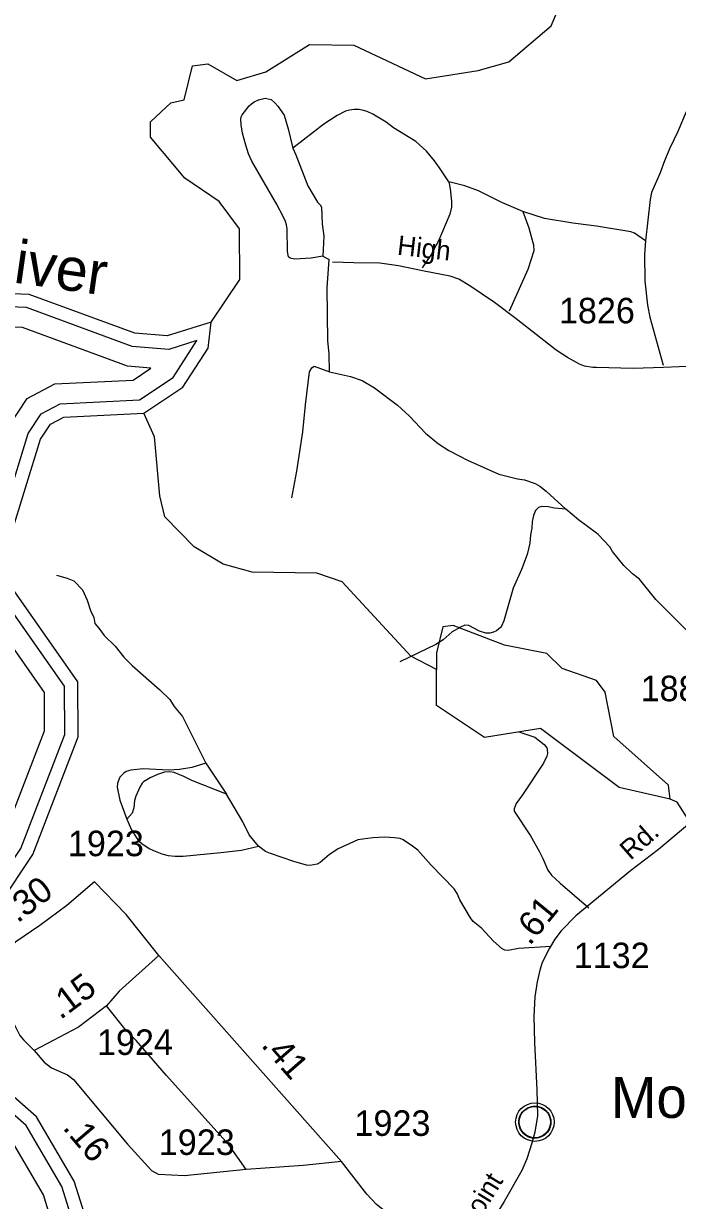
# Model space of a CAD drawing. Extents: x 2104537 to 2336408, y 34176 to 229611.
# Drawn here: x 2193201 to 2196405, y 68278 to 74040 of the extents above; entities that cross this region are included whole.
import ezdxf

# ---------------------------------------------------------------- set-up
doc = ezdxf.new("R2010")
doc.units = 0
for name, color, linetype in [('Exist Civil Demographics Community CELL', 7, 'Continuous'), ('Exist Civil Demographics Community Label', 7, 'Continuous'), ('Exist Hydrographic Buffer Line', 7, 'Continuous'), ('Exist Hydrographic Creek Single Shore', 7, 'Continuous'), ('Exist Hydrographic Misc Water Feature', 7, 'Continuous'), ('Exist Hydrographic River Shore', 7, 'Continuous'), ('Exist Hydrographic River Shore Label', 7, 'Continuous'), ('Exist Road Non-System Type 51', 7, 'Continuous'), ('Exist Road Secondary Mileage Hundredths English Label', 7, 'Continuous'), ('Exist Road Secondary Type 51 Attributed', 7, 'Continuous'), ('Exist Road Secondary Type 51 Label', 7, 'Continuous'), ('Exist Road Secondary Type 51 Number Label', 7, 'Continuous')]:
    doc.layers.add(name, color=color, linetype=linetype)

msp = doc.modelspace()

# ---------------------------------------------------------------- linework, layer by layer
at = {"layer": 'Exist Civil Demographics Community CELL'}
msp.add_lwpolyline([(2195628.7, 68673.7), (2195629.7, 68679.3), (2195631.5, 68685.9), (2195634.4, 68693.1), (2195637.3, 68698.8), (2195640.7, 68704.6), (2195644.4, 68709.7), (2195648.4, 68714.1), (2195653, 68718.7), (2195658.5, 68723.2), (2195663.9, 68726.9), (2195668.8, 68729.8), (2195673.9, 68732.2), (2195679.3, 68734.5), (2195685, 68736.3), (2195689.3, 68737.5), (2195694.1, 68738.2), (2195698.3, 68739), (2195704.6, 68739.2), (2195709.1, 68739.1), (2195714.7, 68738.8), (2195719.6, 68738.1), (2195724.5, 68737.1), (2195729.5, 68735.7), (2195734.7, 68733.8), (2195741.4, 68730.9), (2195747.6, 68727.4), (2195752.7, 68723.8), (2195757.8, 68719.8), (2195761.2, 68716.7), (2195765.3, 68712.3), (2195769.1, 68707.6), (2195772.2, 68703), (2195775.3, 68698), (2195777.8, 68692.8), (2195779.8, 68687.8), (2195781.4, 68682.8), (2195782.7, 68678.2), (2195783.8, 68672.2), (2195784.4, 68667.5), (2195784.7, 68661.5), (2195784.5, 68655.7), (2195783.9, 68650), (2195783, 68644.5), (2195781.3, 68638.4), (2195779.4, 68632.5), (2195777.2, 68627.4), (2195774, 68621.4), (2195770.7, 68616.1), (2195767.3, 68611.4), (2195763, 68606.7), (2195757.7, 68601.7), (2195752.7, 68597.6), (2195747.7, 68594.2), (2195743.4, 68591.7), (2195736.6, 68588.4), (2195729.4, 68585.7), (2195723.5, 68584.2), (2195716.9, 68582.9), (2195712.4, 68582.5), (2195708, 68582.2), (2195702.4, 68582.2), (2195698.1, 68582.6), (2195692.5, 68583.4), (2195686.5, 68584.7), (2195682, 68586), (2195676.8, 68587.8), (2195672.2, 68589.8), (2195668.3, 68592.1), (2195661.5, 68596.1), (2195655.9, 68600.4), (2195651, 68604.9), (2195646.5, 68609.8), (2195643.3, 68613.7), (2195640.4, 68617.9), (2195636.3, 68625), (2195634.5, 68628.5), (2195632.8, 68632.6), (2195630.2, 68640.8), (2195628.7, 68647.8), (2195628, 68653), (2195627.7, 68659.3), (2195627.6, 68664), (2195628.2, 68670.4)], close=True, dxfattribs=at)
for centre, radius in [((2195706.3, 68661.3), 94.3), ((2195706, 68661.6), 76.7)]:
    msp.add_circle(centre, radius, dxfattribs=at)
at = {"layer": 'Exist Hydrographic Buffer Line'}
for points in [[(2194050.2, 72487.5), (2193912.2, 72444), (2193732.4, 72458.7), (2193215.8, 72648.7), (2192875.6, 72661.9), (2192520.7, 72871), (2192188.2, 72927.8), (2192038.1, 73067.6), (2191976.1, 73208.2), (2191975, 73364)], [(2193825.2, 72352.4), (2193711, 72361.7), (2193196.4, 72550.9), (2192847, 72564.5), (2192486.3, 72777.1), (2192164, 72832.1)], [(2193769.4, 72196.7), (2193933.8, 72306.6), (2194050.2, 72487.5)], [(2193737.4, 72293.8), (2193825.2, 72352.4)], [(2193346.9, 68149.6), (2193298.6, 68305.6), (2193136.8, 68581.4), (2192844.6, 68836.2), (2192744.7, 69162), (2192677.5, 69255.2), (2192561.6, 69331.1), (2192561.6, 69585), (2192739.6, 69767), (2192974.9, 69861.3), (2193100.3, 70047), (2193304.3, 70577), (2193303.1, 70763.9), (2193008.1, 71185.1), (2192953.9, 71332.4), (2192974.8, 71560), (2193133.8, 72074.7), (2193218.8, 72204), (2193354.4, 72275.5), (2193737.4, 72293.8)], [(2193439.2, 68184.2), (2193389.3, 68345.6), (2193213.6, 68645.1), (2192930.5, 68891.9), (2192834.1, 69206.4), (2192746.6, 69327.5), (2192660.1, 69384.2), (2192660.1, 69544.9), (2192795.5, 69683.3), (2193039.6, 69781.2), (2193188.2, 70001.2), (2193402.9, 70559.1), (2193401.3, 70795.3), (2193096, 71231.1), (2193053.9, 71345.5), (2193071.9, 71540.7), (2193223.7, 72032.3), (2193287.1, 72128.7), (2193381, 72178.2), (2193769.4, 72196.7)]]:
    msp.add_lwpolyline(points, dxfattribs=at)
at = {"layer": 'Exist Hydrographic Creek Single Shore'}
msp.add_lwpolyline([(2194120.7, 72578.4), (2194260.7, 72785.8), (2194259.7, 73035.1), (2194158.6, 73168.3), (2193990.6, 73283.1), (2193822.7, 73483.2), (2193822.7, 73558.7), (2193921.8, 73651.8), (2193988.6, 73667), (2194028.6, 73833.5), (2194103.6, 73841.9), (2194245.7, 73760.4), (2194387.6, 73803.7), (2194602.7, 73937.3), (2194819.7, 73933.1), (2195170.7, 73768.9), (2195428.7, 73809.8), (2195578.8, 73852.9), (2195785.7, 74029.3), (2195949.7, 74413.2), (2196198.2, 74607.7)], dxfattribs=at)
at = {"layer": 'Exist Hydrographic Misc Water Feature'}
for points in [[(2195223.6, 70877.4), (2195098.8, 70942.2), (2194762.7, 71306.2), (2194637.8, 71348.1), (2194320.8, 71354.1), (2194178.7, 71393), (2194036.8, 71477.7), (2193893.7, 71624.9), (2193868.6, 71727.1), (2193841.8, 72016.3), (2193790.7, 72132.1)], [(2196369.7, 70241.8), (2196360.6, 70310.9), (2196092.6, 70549), (2196049.8, 70766.3), (2196007.7, 70822.9), (2195840.6, 70881.9), (2195764.8, 70955.6), (2195556.6, 70995.7), (2195305.6, 71092.4), (2195255.6, 71086.7), (2195223.6, 70959.4), (2195223.6, 70877.4)], [(2196369.7, 70241.8), (2196119.7, 70299.1), (2195733.8, 70588.7), (2195459.6, 70544.8), (2195224.7, 70700.2), (2195223.6, 70877.4)], [(2198218.8, 69113.6), (2197653.7, 68986.7), (2197403.7, 68991.5), (2197185.8, 69048.2), (2197076.7, 69155.3), (2196816.7, 69531.1), (2196664.7, 69819.5), (2196403.7, 70228), (2196369.7, 70241.8)]]:
    msp.add_lwpolyline(points, dxfattribs=at)
at = {"layer": 'Exist Hydrographic River Shore'}
for points in [[(2194120.7, 72578.4), (2193904.7, 72510.4), (2193746.6, 72523.4), (2193228.7, 72713.8), (2192894.6, 72726.8), (2192543.6, 72933.7), (2192218.6, 72989.2), (2192092.7, 73106.4), (2192041.6, 73222.3), (2192040.6, 73364.9)], [(2193790.7, 72132.1), (2193981.6, 72259.6), (2194104.7, 72450.8), (2194120.7, 72578.4)], [(2193500.8, 68207.2), (2193449.7, 68372.2), (2193264.8, 68687.5), (2192987.7, 68929.1), (2192893.6, 69236), (2192792.7, 69375.8), (2192725.7, 69419.7), (2192725.7, 69518.1), (2192832.7, 69627.6), (2193082.7, 69727.8), (2193246.7, 69970.6), (2193468.6, 70547.1), (2193466.7, 70816.2), (2193154.7, 71261.8), (2193120.6, 71354.3), (2193136.6, 71527.9), (2193283.6, 72004.1), (2193332.6, 72078.6), (2193398.7, 72113.4), (2193790.7, 72132.1)]]:
    msp.add_lwpolyline(points, dxfattribs=at)
at = {"layer": 'Exist Road Non-System Type 51'}
for p, q in [((2194667.9, 72900.6), (2194698.1, 72884.9)), ((2194093.4, 70418.9), (2194195.1, 70266))]:
    msp.add_line(p, q, dxfattribs=at)
for points in [[(2196724.4, 73706.7), (2196582.7, 73675), (2196516.9, 73664.1), (2196483.2, 73651.6), (2196463.3, 73637.2), (2196447.9, 73607), (2196407, 73510.4), (2196368.1, 73430.1), (2196340.9, 73368), (2196319.8, 73309.3), (2196276.9, 73212.7), (2196270.4, 73179), (2196248.1, 72976.7)], [(2194667.9, 72900.6), (2194610, 72891.8), (2194528.2, 72886.8), (2194507.9, 72890.5), (2194499.9, 72898.2), (2194493.5, 72924.3), (2194493.3, 73035.2), (2194490.1, 73054.3), (2194483.8, 73071.1), (2194475.4, 73092.3), (2194440.6, 73157.6), (2194319.6, 73366.3), (2194303.2, 73402), (2194290.6, 73444.3), (2194274, 73503.6), (2194266.9, 73543.5), (2194265.1, 73571.4), (2194267.7, 73582.2), (2194272.8, 73593.5), (2194306.1, 73636.2), (2194317.5, 73646.5), (2194330.1, 73656.1), (2194351.9, 73665.5), (2194385.2, 73673.7), (2194413.7, 73667.3), (2194432, 73651.5), (2194446.2, 73635.8), (2194477.5, 73590.9), (2194497.8, 73524.2), (2194519.6, 73430)], [(2195283.8, 73264), (2195238.6, 73334.1), (2195214, 73367.7), (2195174.5, 73415.7), (2195123, 73462.6), (2195014, 73529), (2194978.1, 73557.6), (2194912.9, 73595.6), (2194884.7, 73609.6), (2194866, 73614.6), (2194844.5, 73618.9), (2194820.5, 73619.7), (2194798.5, 73616.2), (2194778.7, 73610), (2194737, 73589.5), (2194671.5, 73546.5), (2194519.6, 73430)], [(2194519.6, 73430), (2194535.4, 73396.9), (2194593.5, 73245.8), (2194641.2, 73165.8), (2194653.7, 73152.8), (2194661, 73140.8), (2194663.7, 73058.4), (2194672.7, 72998.6), (2194667.9, 72900.6)], [(2195283.8, 73264), (2195291.7, 73230.7), (2195298.4, 73170.9), (2195297.5, 73140.7), (2195289.3, 73106.7), (2195235, 72979.8), (2195196.2, 72905.5), (2195153.3, 72844.3)], [(2195647.8, 73118.9), (2195544.7, 73163.8), (2195430, 73220.5), (2195363.5, 73245.7), (2195283.8, 73264)], [(2195647.8, 73118.9), (2195676.5, 73039.6), (2195693.4, 72979.9), (2195699.5, 72956.1), (2195701.5, 72926.5), (2195671.2, 72835.6), (2195580.3, 72632)], [(2196007.7, 73047.6), (2195982.1, 73051.7), (2195892.1, 73062.6), (2195752.5, 73085), (2195647.8, 73118.9)], [(2196248.1, 72976.7), (2196194.7, 73013.8), (2196176.7, 73020.1), (2196007.7, 73047.6)], [(2196248.1, 72976.7), (2196242.8, 72908.6), (2196244.6, 72780.6), (2196258.1, 72660.6), (2196269.1, 72602.9), (2196334.1, 72367.8)], [(2194699.9, 72334.3), (2194699, 72422.6), (2194692, 72486.4), (2194688.5, 72746.3), (2194698.1, 72884.9)], [(2194516.1, 71718.1), (2194540.3, 71848.6), (2194569.9, 72040.9), (2194582, 72172.9), (2194601.2, 72334.9), (2194613.1, 72354), (2194625.4, 72362.7), (2194699.9, 72334.3)], [(2194699.9, 72334.3), (2194803.5, 72312.3), (2194859.9, 72292.5), (2194920.5, 72255.9), (2195033.7, 72171.4), (2195092.4, 72118.1), (2195169.6, 72034.9), (2195234.5, 71981.8), (2195284.7, 71948.7), (2195375.3, 71901.7), (2195530.2, 71833.7), (2195620.6, 71811), (2195654.6, 71805.4), (2195708.1, 71788), (2195731.1, 71774.1), (2195761.5, 71750.5), (2195857.2, 71661.4)], [(2195857.2, 71661.4), (2195802.2, 71667.1), (2195771.2, 71673.9), (2195740.4, 71674.5), (2195724.5, 71670.2), (2195708.5, 71656.1), (2195698.8, 71631.7), (2195693.3, 71601.6), (2195691.7, 71569.8), (2195684.2, 71535.8), (2195680.8, 71495.5), (2195667.9, 71440.7), (2195640.3, 71367), (2195599.5, 71276), (2195553.4, 71116.1), (2195542.1, 71089.7), (2195537, 71083.6), (2195517.3, 71066.6), (2195504.1, 71059.3), (2195485.6, 71055.4), (2195465.3, 71055.5), (2195434.3, 71064.3), (2195382, 71091.8), (2195362.4, 71094.2), (2195341.8, 71085.1), (2195301.7, 71061.2), (2195256.6, 71022.1), (2195220.1, 71000.1), (2195044.9, 70914.9)], [(2196007.7, 71544.4), (2195919.2, 71610.7), (2195857.2, 71661.4)], [(2196764.2, 70853.2), (2196719.1, 70879), (2196581.8, 70975.2), (2196486.9, 71038), (2196446.6, 71071.3), (2196298.8, 71220.5), (2196219.4, 71319.1), (2196184.8, 71346), (2196142.3, 71385.6), (2196087.2, 71454.9), (2196072.9, 71478.4), (2196016.3, 71537.9), (2196007.7, 71544.4)], [(2193362.8, 71339.1), (2193415, 71324), (2193447.3, 71310.6), (2193489.7, 71266.8), (2193512.4, 71217.1), (2193529.1, 71165.3), (2193545.5, 71131.5), (2193550.2, 71101.6), (2193570.1, 71079.9), (2193596.6, 71044.3), (2193649.4, 70991.1), (2193692.3, 70937.4), (2193732.6, 70896.3), (2193868.4, 70777.9), (2193917, 70730.3), (2193939.3, 70696.8), (2193980.1, 70647.4), (2194093.4, 70418.9)], [(2195627.6, 70572.7), (2195705.8, 70545.6), (2195752.3, 70510.2), (2195764.8, 70494.2), (2195766.6, 70484.7), (2195767.6, 70465.6), (2195765, 70452.2), (2195747.6, 70418.1), (2195645.5, 70262.9), (2195614.2, 70220.6), (2195603.9, 70195.8), (2195604.7, 70184.3), (2195684.3, 70063.4), (2195727.5, 69987.7), (2195745.8, 69951.9), (2195769.7, 69895.1), (2195786.9, 69870.8), (2195829.5, 69831.2), (2195971.2, 69711.1)], [(2194093.4, 70418.9), (2194025.4, 70397.9), (2193965.5, 70386.9), (2193913, 70384.9), (2193787.4, 70391), (2193726.3, 70384.9), (2193703.5, 70377.8), (2193692.2, 70370.2), (2193673.5, 70350.8), (2193661.7, 70320.2), (2193659.4, 70300.6), (2193673.3, 70237.3), (2193706.9, 70143.8)], [(2194195.1, 70266), (2194024.9, 70333.6), (2193985.9, 70353.4), (2193939.7, 70372.6), (2193917.8, 70376.6), (2193891.8, 70374.2), (2193857.8, 70363.7), (2193822, 70347.3), (2193788.2, 70327), (2193782.5, 70319.9), (2193770.6, 70300.7), (2193751.1, 70257.5), (2193745.4, 70236.3), (2193741.8, 70200.3), (2193732.4, 70174.2), (2193706.9, 70143.8)], [(2194352.6, 70012.3), (2194305.8, 70067.3), (2194275.2, 70130.9), (2194195.1, 70266)], [(2193706.9, 70143.8), (2193729.5, 70091.9), (2193762.6, 70040.7), (2193780.4, 70024.6), (2193816.7, 70001), (2193838.4, 69990.4), (2193878.8, 69973.9), (2193908.9, 69966.4), (2193943.2, 69962.8), (2193982.9, 69963.3), (2194167, 69981.7), (2194268.9, 69992.9), (2194352.6, 70012.3)], [(2195783.5, 69520.8), (2195625.5, 69510.7), (2195575.7, 69502.1), (2195559.7, 69503.8), (2195545.4, 69509.6), (2195503.1, 69546.9), (2195444.3, 69610.3), (2195404.6, 69643.9), (2195391.5, 69661.5), (2195338.4, 69748.9), (2195325.9, 69780.9), (2195311.5, 69802.8), (2195198, 69919.2), (2195133.1, 69992.3), (2195106.9, 70011.8), (2195060.9, 70042.9), (2195046.3, 70049.1), (2195016.2, 70052.6), (2194970.3, 70056.1), (2194912.2, 70053.3), (2194839.1, 70043.3), (2194743.1, 69999.2), (2194699.3, 69970.8), (2194653.6, 69932), (2194640.3, 69923.7), (2194604.1, 69917.5), (2194587.7, 69919.2), (2194525.7, 69936.4), (2194411, 69976.7), (2194386.9, 69986.4), (2194352.6, 70012.3)], [(2194291.3, 68429.1), (2194206.8, 68550), (2193901, 68888.7), (2193752.7, 69060.8), (2193697.7, 69118), (2193606.9, 69229.9)], [(2194758.4, 68468.4), (2194571.2, 68448.3), (2194291.3, 68429.1)], [(2194291.3, 68429.1), (2193989.4, 68398.9), (2193862.5, 68405), (2193830.3, 68423.1)]]:
    msp.add_lwpolyline(points, dxfattribs=at)
at = {"layer": 'Exist Road Secondary Type 51 Attributed'}
for points in [[(2196490.3, 72362.1), (2196336.7, 72355.4), (2196187.6, 72350.8), (2196007.7, 72355.5), (2195990.4, 72355), (2195949.8, 72363), (2195924.1, 72372.4), (2195866, 72405.1), (2195810.3, 72441.2), (2195614.5, 72593.4), (2195507.6, 72673.3), (2195387.1, 72756.2), (2195332.9, 72787.8), (2195290.7, 72802.9), (2195164.2, 72827), (2195037.7, 72854.1), (2194945.8, 72866.1), (2194819.3, 72867.7), (2194713.9, 72872.2)], [(2196897.3, 70613.2), (2196765.7, 70473.5), (2196680.7, 70368.3), (2196465.7, 70125.4), (2196311.6, 69995.5), (2196174, 69891.1), (2195907.2, 69671), (2195834.5, 69598.3), (2195803.3, 69556.7), (2195777.3, 69513.3), (2195742.6, 69442.2), (2195729.7, 69405.3), (2195717.8, 69347.8), (2195706.3, 69273.8), (2195701.1, 69178.5), (2195704.6, 69050.6), (2195716.3, 68819.1), (2195718.5, 68692.5), (2195705.5, 68611.5), (2195692, 68557.3), (2195667.3, 68481.4), (2195641.9, 68424.8), (2195555.6, 68272.2), (2195358.5, 67947.7)], [(2193864.6, 69476.7), (2193703.9, 69677.8), (2193548.5, 69837.3), (2193413.6, 69722.5), (2193280.8, 69623.8), (2193164, 69543.2), (2193093.5, 69482.8), (2193069.4, 69438.5)], [(2193069.4, 69438.5), (2193063.3, 69406.2), (2193067.4, 69327.6), (2193146.6, 69156.7), (2193183.6, 69085.2), (2193200, 69063.5), (2193252.6, 69011.4)], [(2193864.6, 69476.7), (2193669.3, 69301.5), (2193606.9, 69229.9), (2193470, 69126.2), (2193252.6, 69011.4)], [(2195358.5, 67947.7), (2195184.8, 68062.8), (2195085.5, 68135.6), (2194930, 68257.7), (2194883.1, 68309.1), (2194758.4, 68468.4), (2193864.6, 69476.7)], [(2193252.6, 69011.4), (2193301.9, 68955), (2193338.4, 68927.4), (2193416.8, 68892.4), (2193445.3, 68870.5), (2193709.5, 68554), (2193830.3, 68423.1)]]:
    msp.add_lwpolyline(points, dxfattribs=at)

# ---------------------------------------------------------------- texts
at = {"layer": 'Exist Civil Demographics Community Label'}
msp.add_text('Monogram', height=200, dxfattribs=at).set_placement((2196078.9, 68681.8))
at = {"layer": 'Exist Hydrographic River Shore Label'}
msp.add_text('River', height=210, rotation=351.87024, dxfattribs=at).set_placement((2192946.6, 72800.9))
at = {"layer": 'Exist Road Secondary Mileage Hundredths English Label'}
for s, rotation, p in [('.30', 37.87361, (2193171.8, 69632.4)), ('.61', 50.78336, (2195680.8, 69521.3)), ('.15', 36.94996, (2193381.8, 69159.7)), ('.41', 311.0417, (2194361.3, 69035.7)), ('.16', 310.25321, (2193389, 68631.7))]:
    msp.add_text(s, height=125, rotation=rotation, dxfattribs=at).set_placement(p)
at = {"layer": 'Exist Road Secondary Type 51 Label'}
for s, rotation, p in [('High ', 353.52069, (2195028.6, 72908.3)), ('Rd.', 41.42113, (2196174.5, 69940.2)), ('Point', 58.30408, (2195401.5, 68128.1))]:
    msp.add_text(s, height=95, rotation=rotation, dxfattribs=at).set_placement(p)
at = {"layer": 'Exist Road Secondary Type 51 Number Label'}
for s, p in [('1826', (2195824.1, 72571.9)), ('1885', (2196224.2, 70721.8)), ('1923', (2193418.3, 69963.2)), ('1132', (2195896.4, 69415)), ('1924', (2193561.2, 68989.9)), ('1923', (2194822.5, 68593.8)), ('1923', (2193863.7, 68500.3))]:
    msp.add_text(s, height=125, dxfattribs=at).set_placement(p)

doc.saveas('drawing.dxf')
